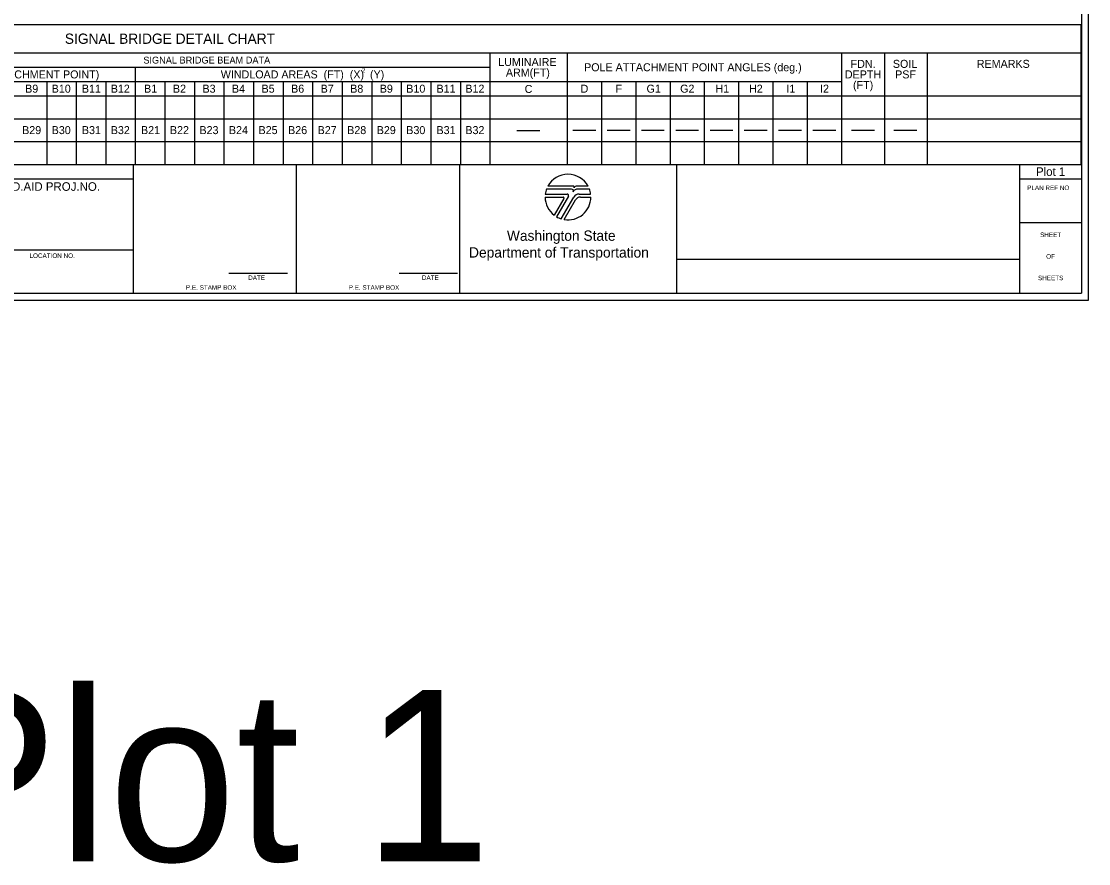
# Model space of a CAD drawing. Extents: x 99999.3 to 100015.8, y 99995 to 100010.4.
# Drawn here: x 100006.47 to 100015.81, y 99995.01 to 100002.38 of the extents above; entities that cross this region are included whole.
import ezdxf

# ---------------------------------------------------------------- set-up
doc = ezdxf.new("R2010")
doc.units = 0
for name, color, linetype in [('Level 40', 7, 'Continuous'), ('Level 51', 7, 'Continuous'), ('SH_GI_PlotLimits', 7, 'Continuous'), ('SH_GI_SheetBorder', 7, 'Continuous'), ('SH_GI_SheetLocationText', 7, 'Continuous'), ('SH_GI_SheetTextInCells', 7, 'Continuous'), ('SH_GI_WSDOTLogo', 7, 'Continuous')]:
    doc.layers.add(name, color=color, linetype=linetype)

msp = doc.modelspace()

# ---------------------------------------------------------------- linework, layer by layer
at = {"layer": 'Level 40'}
for p, q in [((100000, 100002.3509), (100015.7438, 100002.3509)), ((100015.7438, 100002.3509), (100015.7438, 100002.1009)), ((100000, 100002.1009), (100015.7438, 100002.1009)), ((100010.574, 100002.1009), (100010.574, 100001.8509)), ((100011.25, 100002.1009), (100011.25, 100001.8509)), ((100013.65, 100002.1009), (100013.65, 100001.8509)), ((100014.025, 100002.1009), (100014.025, 100001.7259)), ((100014.4, 100002.1009), (100014.4, 100001.7259)), ((100015.7438, 100002.1009), (100015.7438, 100001.1259)), ((100004.37, 100001.9759), (100010.574, 100001.9759)), ((100007.472, 100001.9759), (100007.472, 100001.8509)), ((100004.55, 100001.8509), (100013.65, 100001.8509)), ((100006.6965, 100001.8509), (100006.6965, 100001.1259)), ((100006.955, 100001.8509), (100006.955, 100001.1259)), ((100007.2135, 100001.8509), (100007.2135, 100001.1259)), ((100007.472, 100001.8509), (100007.472, 100001.1259)), ((100007.7305, 100001.8509), (100007.7305, 100001.1259)), ((100007.989, 100001.8509), (100007.989, 100001.1259)), ((100008.2475, 100001.8509), (100008.2475, 100001.1259)), ((100008.506, 100001.8509), (100008.506, 100001.1259)), ((100008.7645, 100001.8509), (100008.7645, 100001.1259)), ((100009.023, 100001.8509), (100009.023, 100001.1259)), ((100009.2815, 100001.8509), (100009.2815, 100001.1259)), ((100009.54, 100001.8509), (100009.54, 100001.1259)), ((100009.7985, 100001.8509), (100009.7985, 100001.1259)), ((100010.057, 100001.8509), (100010.057, 100001.1259)), ((100010.3155, 100001.8509), (100010.3155, 100001.1259)), ((100010.574, 100001.8509), (100010.574, 100001.1259)), ((100011.25, 100001.8509), (100011.25, 100001.1259)), ((100011.55, 100001.8509), (100011.55, 100001.1259)), ((100011.85, 100001.8509), (100011.85, 100001.1259)), ((100012.15, 100001.8509), (100012.15, 100001.1259)), ((100012.45, 100001.8509), (100012.45, 100001.1259)), ((100012.75, 100001.8509), (100012.75, 100001.1259)), ((100013.05, 100001.8509), (100013.05, 100001.1259)), ((100013.35, 100001.8509), (100013.35, 100001.1259)), ((100013.65, 100001.8509), (100013.65, 100001.1259)), ((100000, 100001.7259), (100015.7438, 100001.7259)), ((100014.025, 100001.7259), (100014.025, 100001.1259)), ((100014.4, 100001.7259), (100014.4, 100001.1259)), ((100000, 100001.5259), (100015.7438, 100001.5259)), ((100010.8103, 100001.4235), (100010.9103, 100001.4235)), ((100010.9103, 100001.4235), (100011.0103, 100001.4235)), ((100011.3, 100001.4259), (100011.4, 100001.4259)), ((100011.4, 100001.4259), (100011.5, 100001.4259)), ((100011.6, 100001.4259), (100011.7, 100001.4259)), ((100011.7, 100001.4259), (100011.8, 100001.4259)), ((100011.9, 100001.4259), (100012, 100001.4259)), ((100012, 100001.4259), (100012.1, 100001.4259)), ((100012.2, 100001.4259), (100012.3, 100001.4259)), ((100012.3, 100001.4259), (100012.4, 100001.4259)), ((100012.5, 100001.4259), (100012.6, 100001.4259)), ((100012.6, 100001.4259), (100012.7, 100001.4259)), ((100012.8, 100001.4259), (100012.9, 100001.4259)), ((100012.9, 100001.4259), (100013, 100001.4259)), ((100013.1, 100001.4259), (100013.2, 100001.4259)), ((100013.2, 100001.4259), (100013.3, 100001.4259)), ((100013.4, 100001.4259), (100013.5, 100001.4259)), ((100013.5, 100001.4259), (100013.6, 100001.4259)), ((100013.7389, 100001.4259), (100013.8389, 100001.4259)), ((100013.8389, 100001.4259), (100013.9389, 100001.4259)), ((100014.1092, 100001.4259), (100014.2092, 100001.4259)), ((100014.2092, 100001.4259), (100014.3092, 100001.4259)), ((100000.3, 100001.3259), (100015.7438, 100001.3259)), ((100000, 100001.1259), (100015.7438, 100001.1259))]:
    msp.add_line(p, q, dxfattribs=at)
at = {"layer": 'SH_GI_PlotLimits'}
msp.add_lwpolyline([(99999.3125, 99999.9375), (100015.8125, 99999.9375), (100015.8125, 100010.4375), (99999.3125, 100010.4375)], close=True, dxfattribs=at)
at = {"layer": 'SH_GI_SheetBorder'}
for p, q in [((100015.75, 100010.375), (100015.75, 100000)), ((100000, 100001.1259), (100015.75, 100001.1259)), ((100007.4566, 100000), (100007.4566, 100001.1259)), ((100008.8828, 100000), (100008.8828, 100001.1259)), ((100010.3089, 100001.1259), (100010.3089, 100000)), ((100012.2055, 100001.1259), (100012.2055, 100000)), ((100015.2079, 100001.1259), (100015.2079, 100000)), ((100000, 100001.0008), (100007.4566, 100001.0008)), ((100015.2079, 100001.0008), (100015.75, 100001.0008)), ((100015.2079, 100000.6176), (100015.75, 100000.6176)), ((100007.4566, 100000.3753), (100005.4466, 100000.3753)), ((100012.2055, 100000.2955), (100015.2079, 100000.2955)), ((100008.2903, 100000.1733), (100008.802, 100000.1733)), ((100009.7797, 100000.1733), (100010.2914, 100000.1733)), ((100000, 100000), (100015.75, 100000))]:
    msp.add_line(p, q, dxfattribs=at)
at = {"layer": 'SH_GI_WSDOTLogo'}
for p, q in [((100011.303, 100000.9354), (100011.0815, 100000.9354)), ((100011.433, 100000.9354), (100011.3351, 100000.9354)), ((100011.0572, 100000.84), (100011.2148, 100000.84)), ((100011.059, 100000.8661), (100011.2496, 100000.8661)), ((100011.2894, 100000.9094), (100011.0697, 100000.9094)), ((100011.261, 100000.8464), (100011.1567, 100000.6672)), ((100011.1989, 100000.6487), (100011.3089, 100000.839)), ((100011.343, 100000.9094), (100011.3429, 100000.9094)), ((100011.4448, 100000.9094), (100011.343, 100000.9094)), ((100011.3558, 100000.8661), (100011.4555, 100000.8661)), ((100011.3655, 100000.8394), (100011.4572, 100000.8394)), ((100011.222, 100000.8277), (100011.1364, 100000.6807)), ((100011.2244, 100000.6428), (100011.3242, 100000.8156))]:
    msp.add_line(p, q, dxfattribs=at)
for centre, radius, start, end in [((100011.2572, 100000.84), 0.2, 28.47865, 151.53204), ((100011.303, 100000.9263), 0.00903, 329.87418, 90.00328), ((100011.3352, 100000.9066), 0.0287, 90.00721, 148.16763), ((100011.2572, 100000.84), 0.2, 179.99864, 232.84327), ((100011.2572, 100000.84), 0.2, 159.69598, 172.50569), ((100011.2149, 100000.8318), 0.0082, 329.74356, 90), ((100011.2572, 100000.84), 0.2, 260.54554, 359.80857), ((100011.2497, 100000.853), 0.0131, 329.76834, 90), ((100011.2894, 100000.8946), 0.0148, 327.8418, 89.99855), ((100011.3429, 100000.861), 0.0484, 89.99529, 147.82376), ((100011.3558, 100000.8119), 0.0542, 90, 149.99738), ((100011.3654, 100000.7918), 0.0476, 90, 150.05432), ((100011.2572, 100000.84), 0.2, 7.49431, 20.29406), ((100011.2572, 100000.84), 0.2, 239.79292, 253.0448)]:
    msp.add_arc(centre, radius, start, end, dxfattribs=at)

# ---------------------------------------------------------------- texts
at = {"layer": 'Level 51'}
for s, height, p in [('SIGNAL BRIDGE DETAIL CHART', 0.09, (100006.8553, 100002.1809)), ('SIGNAL BRIDGE BEAM DATA', 0.06, (100007.5422, 100002.0084)), ('LUMINAIRE', 0.07, (100010.6473, 100001.9871)), ('2', 0.04, (100009.4536, 100001.9273)), ('ARM(FT)', 0.07, (100010.714, 100001.8947)), ('POLE ATTACHMENT POINT ANGLES (deg.)', 0.07, (100011.3983, 100001.9409)), ('FDN.', 0.07, (100013.7299, 100001.9708)), ('SOIL', 0.07, (100014.0996, 100001.9708)), ('REMARKS', 0.07, (100014.8343, 100001.9708)), ('OFFSET DISTANCES (FT) (Z) (POLE  TO ATTACHMENT POINT)', 0.07, (100004.3796, 100001.8784)), ('WINDLOAD AREAS  (FT)  (X)  (Y)', 0.07, (100008.2197, 100001.8784)), ('DEPTH', 0.07, (100013.6797, 100001.8784)), ('PSF', 0.07, (100014.1194, 100001.8784)), ('B9', 0.07, (100006.5082, 100001.7534)), ('B10', 0.07, (100006.7403, 100001.7534)), ('B11', 0.07, (100007.0046, 100001.7534)), ('B12', 0.07, (100007.2573, 100001.7534)), ('B1', 0.07, (100007.5485, 100001.7534)), ('B2', 0.07, (100007.801, 100001.7534)), ('B3', 0.07, (100008.0595, 100001.7534)), ('B4', 0.07, (100008.3174, 100001.7534)), ('B5', 0.07, (100008.5765, 100001.7534)), ('B6', 0.07, (100008.835, 100001.7534)), ('B7', 0.07, (100009.0935, 100001.7534)), ('B8', 0.07, (100009.352, 100001.7534)), ('B9', 0.07, (100009.6105, 100001.7534)), ('B10', 0.07, (100009.8426, 100001.7534)), ('B11', 0.07, (100010.107, 100001.7534)), ('B12', 0.07, (100010.3596, 100001.7534)), ('C', 0.07, (100010.8784, 100001.751)), ('D', 0.07, (100011.3677, 100001.7534)), ('F', 0.07, (100011.6736, 100001.7534)), ('G1', 0.07, (100011.9446, 100001.7534)), ('G2', 0.07, (100012.2386, 100001.7534)), ('H1', 0.07, (100012.5472, 100001.7534)), ('H2', 0.07, (100012.8413, 100001.7534)), ('I1', 0.07, (100013.1683, 100001.7534)), ('I2', 0.07, (100013.4624, 100001.7534)), ('(FT)', 0.07, (100013.7511, 100001.786)), ('B29', 0.07, (100006.4818, 100001.3909)), ('B30', 0.07, (100006.7403, 100001.3909)), ('B31', 0.07, (100007.0046, 100001.3909)), ('B32', 0.07, (100007.2573, 100001.3909)), ('B21', 0.07, (100007.522, 100001.3909)), ('B22', 0.07, (100007.7746, 100001.3909)), ('B23', 0.07, (100008.0331, 100001.3909)), ('B24', 0.07, (100008.2909, 100001.3909)), ('B25', 0.07, (100008.5501, 100001.3909)), ('B26', 0.07, (100008.8086, 100001.3909)), ('B27', 0.07, (100009.0671, 100001.3909)), ('B28', 0.07, (100009.3256, 100001.3909)), ('B29', 0.07, (100009.5841, 100001.3909)), ('B30', 0.07, (100009.8426, 100001.3909)), ('B31', 0.07, (100010.107, 100001.3909)), ('B32', 0.07, (100010.3596, 100001.3909))]:
    msp.add_text(s, height=height, dxfattribs=at).set_placement(p)
at = {"layer": 'SH_GI_SheetBorder'}
msp.add_text('PLAN REF NO', height=0.040032, dxfattribs=at).set_placement((100015.2747, 100000.9008))
at = {"layer": 'SH_GI_SheetLocationText'}
for height, p in [(0.075, (100015.3518, 100001.025)), (1.5, (100005.4547, 99995.0267))]:
    msp.add_text('Plot 1', height=height, dxfattribs=at).set_placement(p)
at = {"layer": 'SH_GI_SheetTextInCells'}
for s, height, p in [('FED.AID PROJ.NO.', 0.07506, (100006.2652, 100000.8945)), ('Washington State', 0.090072, (100010.7229, 100000.4571)), ('SHEET', 0.04003, (100015.3877, 100000.4896)), ('Department of Transportation', 0.090072, (100010.3916, 100000.3101)), ('LOCATION NO.', 0.040032, (100006.5465, 100000.3067)), ('OF', 0.04003, (100015.4406, 100000.3008)), ('DATE', 0.04003, (100008.4597, 100000.1141)), ('DATE', 0.04003, (100009.9794, 100000.1141)), ('SHEETS', 0.04003, (100015.3698, 100000.112)), ('P.E. STAMP BOX', 0.040032, (100007.915, 100000.0286)), ('P.E. STAMP BOX', 0.040032, (100009.339, 100000.0286))]:
    msp.add_text(s, height=height, dxfattribs=at).set_placement(p)

doc.saveas('drawing.dxf')
